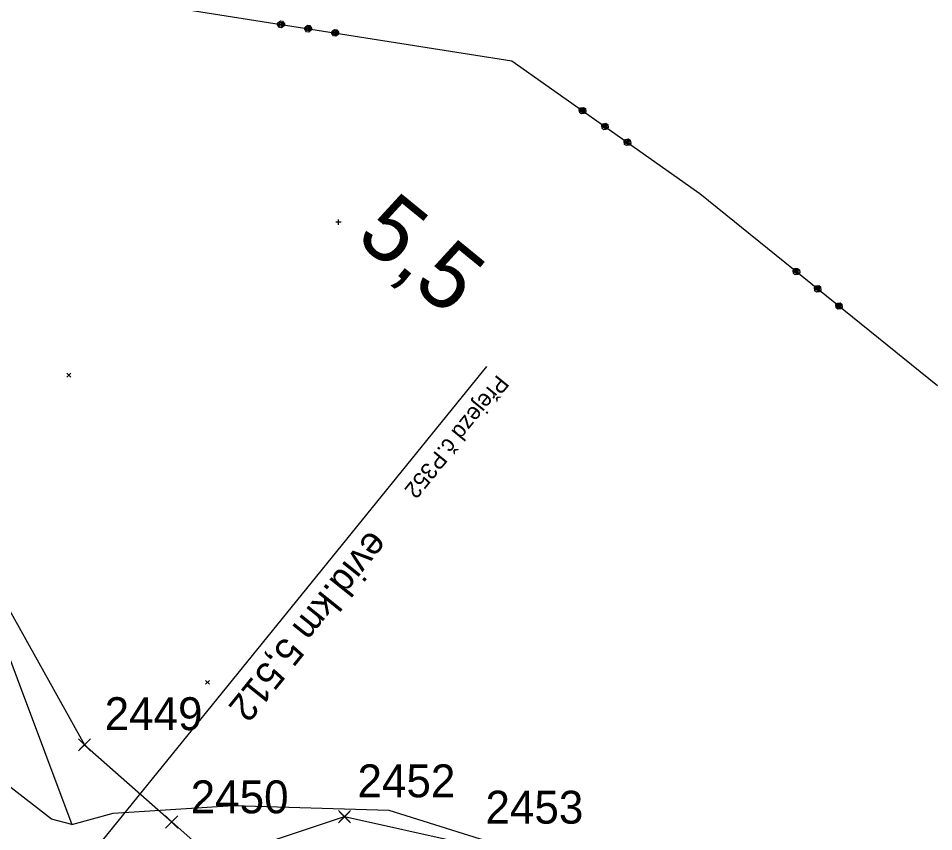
# Model space of a CAD drawing. Extents: x -866402 to -860377, y -1041908 to -1038598.
# Drawn here: x -864812.3 to -864728.8, y -1041184.8 to -1041110.6 of the extents above; entities that cross this region are included whole.
import ezdxf

# ---------------------------------------------------------------- set-up
doc = ezdxf.new("R2010")
doc.units = 0
for name, color, linetype in [('SZDC', 7, 'Continuous'), ('Vrstva 1', 7, 'Continuous'), ('Vrstva 4', 7, 'Continuous'), ('Vrstva 49', 7, 'Continuous'), ('Vrstva 60', 7, 'Continuous'), ('Vrstva 7', 7, 'Continuous')]:
    doc.layers.add(name, color=color, linetype=linetype)

msp = doc.modelspace()

# ---------------------------------------------------------------- linework, layer by layer
at = {"layer": 'SZDC'}
msp.add_lwpolyline([(-864875.011, -1041097.529), (-864834.001, -1041135.622), (-864824.11, -1041144.811), (-864806.24, -1041176.841), (-864798.286, -1041183.888), (-864794.374, -1041187.354), (-864782.521, -1041183.403), (-864771.624, -1041185.807), (-864744.425, -1041200.941), (-864739.358, -1041206.135), (-864711.79, -1041234.401), (-864706.957, -1041253.226), (-864707.405, -1041272.394), (-864707.88, -1041292.731), (-864695.12, -1041304.731)], dxfattribs=at)
at = {"layer": 'Vrstva 1'}
for p, q in [((-864804.23, -1041108.61), (-864767.26, -1041114.45)), ((-864804.23, -1041108.61), (-864767.26, -1041114.45)), ((-864788.625, -1041111.176), (-864788.593, -1041110.978)), ((-864788.625, -1041111.176), (-864788.593, -1041110.978)), ((-864788.458, -1041111.405), (-864788.625, -1041111.176)), ((-864788.458, -1041111.405), (-864788.625, -1041111.176)), ((-864788.593, -1041110.978), (-864788.365, -1041110.812)), ((-864788.593, -1041110.978), (-864788.365, -1041110.812)), ((-864788.495, -1041110.994), (-864788.526, -1041111.191)), ((-864788.495, -1041110.994), (-864788.526, -1041111.191)), ((-864788.526, -1041111.191), (-864788.443, -1041111.306)), ((-864788.526, -1041111.191), (-864788.443, -1041111.306)), ((-864788.261, -1041111.436), (-864788.458, -1041111.405)), ((-864788.261, -1041111.436), (-864788.458, -1041111.405)), ((-864788.443, -1041111.306), (-864788.38, -1041110.911)), ((-864788.443, -1041111.306), (-864788.38, -1041110.911)), ((-864788.38, -1041110.911), (-864788.183, -1041110.942)), ((-864788.38, -1041110.911), (-864788.183, -1041110.942)), ((-864788.365, -1041110.812), (-864788.167, -1041110.843)), ((-864788.365, -1041110.812), (-864788.167, -1041110.843)), ((-864788.281, -1041110.926), (-864788.344, -1041111.321)), ((-864788.281, -1041110.926), (-864788.344, -1041111.321)), ((-864788.032, -1041111.269), (-864788.261, -1041111.436)), ((-864788.032, -1041111.269), (-864788.261, -1041111.436)), ((-864788.183, -1041110.942), (-864788.245, -1041111.337)), ((-864788.183, -1041110.942), (-864788.245, -1041111.337)), ((-864788.245, -1041111.337), (-864788.131, -1041111.254)), ((-864788.245, -1041111.337), (-864788.131, -1041111.254)), ((-864788.167, -1041110.843), (-864788.001, -1041111.072)), ((-864788.167, -1041110.843), (-864788.001, -1041111.072)), ((-864788.131, -1041111.254), (-864788.1, -1041111.056)), ((-864788.131, -1041111.254), (-864788.1, -1041111.056)), ((-864788.001, -1041111.072), (-864788.032, -1041111.269)), ((-864788.001, -1041111.072), (-864788.032, -1041111.269)), ((-864786.155, -1041111.566), (-864786.124, -1041111.368)), ((-864786.155, -1041111.566), (-864786.124, -1041111.368)), ((-864785.989, -1041111.795), (-864786.155, -1041111.566)), ((-864785.989, -1041111.795), (-864786.155, -1041111.566)), ((-864786.124, -1041111.368), (-864785.895, -1041111.202)), ((-864786.124, -1041111.368), (-864785.895, -1041111.202)), ((-864786.025, -1041111.384), (-864786.056, -1041111.581)), ((-864786.025, -1041111.384), (-864786.056, -1041111.581)), ((-864786.056, -1041111.581), (-864785.973, -1041111.696)), ((-864786.056, -1041111.581), (-864785.973, -1041111.696)), ((-864785.973, -1041111.696), (-864785.911, -1041111.301)), ((-864785.973, -1041111.696), (-864785.911, -1041111.301)), ((-864785.911, -1041111.301), (-864785.713, -1041111.332)), ((-864785.911, -1041111.301), (-864785.713, -1041111.332)), ((-864785.895, -1041111.202), (-864785.698, -1041111.233)), ((-864785.895, -1041111.202), (-864785.698, -1041111.233)), ((-864785.812, -1041111.316), (-864785.874, -1041111.711)), ((-864785.812, -1041111.316), (-864785.874, -1041111.711)), ((-864785.713, -1041111.332), (-864785.776, -1041111.727)), ((-864785.713, -1041111.332), (-864785.776, -1041111.727)), ((-864785.698, -1041111.233), (-864785.531, -1041111.462)), ((-864785.698, -1041111.233), (-864785.531, -1041111.462)), ((-864785.661, -1041111.644), (-864785.63, -1041111.446)), ((-864785.661, -1041111.644), (-864785.63, -1041111.446)), ((-864785.531, -1041111.462), (-864785.563, -1041111.659)), ((-864785.531, -1041111.462), (-864785.563, -1041111.659)), ((-864783.655, -1041111.758), (-864783.426, -1041111.592)), ((-864783.655, -1041111.758), (-864783.426, -1041111.592)), ((-864783.426, -1041111.592), (-864783.228, -1041111.623)), ((-864783.426, -1041111.592), (-864783.228, -1041111.623)), ((-864783.228, -1041111.623), (-864783.062, -1041111.852)), ((-864783.228, -1041111.623), (-864783.062, -1041111.852)), ((-864785.791, -1041111.826), (-864785.989, -1041111.795)), ((-864785.791, -1041111.826), (-864785.989, -1041111.795)), ((-864785.563, -1041111.659), (-864785.791, -1041111.826)), ((-864785.563, -1041111.659), (-864785.791, -1041111.826)), ((-864785.776, -1041111.727), (-864785.661, -1041111.644)), ((-864785.776, -1041111.727), (-864785.661, -1041111.644)), ((-864783.686, -1041111.956), (-864783.655, -1041111.758)), ((-864783.686, -1041111.956), (-864783.655, -1041111.758)), ((-864783.519, -1041112.185), (-864783.686, -1041111.956)), ((-864783.519, -1041112.185), (-864783.686, -1041111.956)), ((-864783.556, -1041111.774), (-864783.587, -1041111.972)), ((-864783.556, -1041111.774), (-864783.587, -1041111.972)), ((-864783.587, -1041111.972), (-864783.504, -1041112.086)), ((-864783.587, -1041111.972), (-864783.504, -1041112.086)), ((-864783.322, -1041112.216), (-864783.519, -1041112.185)), ((-864783.322, -1041112.216), (-864783.519, -1041112.185)), ((-864783.504, -1041112.086), (-864783.441, -1041111.691)), ((-864783.504, -1041112.086), (-864783.441, -1041111.691)), ((-864783.441, -1041111.691), (-864783.244, -1041111.722)), ((-864783.441, -1041111.691), (-864783.244, -1041111.722)), ((-864783.343, -1041111.706), (-864783.405, -1041112.102)), ((-864783.343, -1041111.706), (-864783.405, -1041112.102)), ((-864783.093, -1041112.05), (-864783.322, -1041112.216)), ((-864783.093, -1041112.05), (-864783.322, -1041112.216)), ((-864783.244, -1041111.722), (-864783.306, -1041112.117)), ((-864783.244, -1041111.722), (-864783.306, -1041112.117)), ((-864783.306, -1041112.117), (-864783.192, -1041112.034)), ((-864783.306, -1041112.117), (-864783.192, -1041112.034)), ((-864783.192, -1041112.034), (-864783.161, -1041111.836)), ((-864783.192, -1041112.034), (-864783.161, -1041111.836)), ((-864783.062, -1041111.852), (-864783.093, -1041112.05)), ((-864783.062, -1041111.852), (-864783.093, -1041112.05)), ((-864767.26, -1041114.45), (-864750.13, -1041126.55)), ((-864767.26, -1041114.45), (-864750.13, -1041126.55)), ((-864761.121, -1041118.908), (-864761.005, -1041118.745)), ((-864761.121, -1041118.908), (-864761.005, -1041118.745)), ((-864761.073, -1041119.187), (-864761.121, -1041118.908)), ((-864761.073, -1041119.187), (-864761.121, -1041118.908)), ((-864760.924, -1041118.802), (-864761.039, -1041118.966)), ((-864760.924, -1041118.802), (-864761.039, -1041118.966)), ((-864761.039, -1041118.966), (-864761.015, -1041119.105)), ((-864761.039, -1041118.966), (-864761.015, -1041119.105)), ((-864761.015, -1041119.105), (-864760.784, -1041118.778)), ((-864761.015, -1041119.105), (-864760.784, -1041118.778)), ((-864761.005, -1041118.745), (-864760.727, -1041118.697)), ((-864761.005, -1041118.745), (-864760.727, -1041118.697)), ((-864760.703, -1041118.836), (-864760.934, -1041119.163)), ((-864760.703, -1041118.836), (-864760.934, -1041119.163)), ((-864760.621, -1041118.894), (-864760.852, -1041119.221)), ((-864760.621, -1041118.894), (-864760.852, -1041119.221)), ((-864760.784, -1041118.778), (-864760.621, -1041118.894)), ((-864760.784, -1041118.778), (-864760.621, -1041118.894)), ((-864760.727, -1041118.697), (-864760.563, -1041118.812)), ((-864760.727, -1041118.697), (-864760.563, -1041118.812)), ((-864760.712, -1041119.197), (-864760.597, -1041119.033)), ((-864760.712, -1041119.197), (-864760.597, -1041119.033)), ((-864760.515, -1041119.091), (-864760.631, -1041119.254)), ((-864760.515, -1041119.091), (-864760.631, -1041119.254)), ((-864760.563, -1041118.812), (-864760.515, -1041119.091)), ((-864760.563, -1041118.812), (-864760.515, -1041119.091)), ((-864760.91, -1041119.302), (-864761.073, -1041119.187)), ((-864760.91, -1041119.302), (-864761.073, -1041119.187)), ((-864760.631, -1041119.254), (-864760.91, -1041119.302)), ((-864760.631, -1041119.254), (-864760.91, -1041119.302)), ((-864760.852, -1041119.221), (-864760.712, -1041119.197)), ((-864760.852, -1041119.221), (-864760.712, -1041119.197)), ((-864759.079, -1041120.35), (-864758.964, -1041120.187)), ((-864759.079, -1041120.35), (-864758.964, -1041120.187)), ((-864759.031, -1041120.629), (-864759.079, -1041120.35)), ((-864759.031, -1041120.629), (-864759.079, -1041120.35)), ((-864758.868, -1041120.745), (-864759.031, -1041120.629)), ((-864758.868, -1041120.745), (-864759.031, -1041120.629)), ((-864758.882, -1041120.245), (-864758.997, -1041120.408)), ((-864758.882, -1041120.245), (-864758.997, -1041120.408)), ((-864758.997, -1041120.408), (-864758.973, -1041120.547)), ((-864758.997, -1041120.408), (-864758.973, -1041120.547)), ((-864758.973, -1041120.547), (-864758.742, -1041120.221)), ((-864758.973, -1041120.547), (-864758.742, -1041120.221)), ((-864758.964, -1041120.187), (-864758.685, -1041120.139)), ((-864758.964, -1041120.187), (-864758.685, -1041120.139)), ((-864758.661, -1041120.278), (-864758.892, -1041120.605)), ((-864758.661, -1041120.278), (-864758.892, -1041120.605)), ((-864758.589, -1041120.697), (-864758.868, -1041120.745)), ((-864758.589, -1041120.697), (-864758.868, -1041120.745)), ((-864758.579, -1041120.336), (-864758.81, -1041120.663)), ((-864758.579, -1041120.336), (-864758.81, -1041120.663)), ((-864758.81, -1041120.663), (-864758.671, -1041120.639)), ((-864758.81, -1041120.663), (-864758.671, -1041120.639)), ((-864758.742, -1041120.221), (-864758.579, -1041120.336)), ((-864758.742, -1041120.221), (-864758.579, -1041120.336)), ((-864758.685, -1041120.139), (-864758.521, -1041120.254)), ((-864758.685, -1041120.139), (-864758.521, -1041120.254)), ((-864758.671, -1041120.639), (-864758.555, -1041120.476)), ((-864758.671, -1041120.639), (-864758.555, -1041120.476)), ((-864758.473, -1041120.533), (-864758.589, -1041120.697)), ((-864758.473, -1041120.533), (-864758.589, -1041120.697)), ((-864758.521, -1041120.254), (-864758.473, -1041120.533)), ((-864758.521, -1041120.254), (-864758.473, -1041120.533)), ((-864757.037, -1041121.793), (-864756.922, -1041121.629)), ((-864757.037, -1041121.793), (-864756.922, -1041121.629)), ((-864756.922, -1041121.629), (-864756.643, -1041121.581)), ((-864756.922, -1041121.629), (-864756.643, -1041121.581)), ((-864756.643, -1041121.581), (-864756.479, -1041121.697)), ((-864756.643, -1041121.581), (-864756.479, -1041121.697)), ((-864756.989, -1041122.072), (-864757.037, -1041121.793)), ((-864756.989, -1041122.072), (-864757.037, -1041121.793)), ((-864756.826, -1041122.187), (-864756.989, -1041122.072)), ((-864756.826, -1041122.187), (-864756.989, -1041122.072)), ((-864756.84, -1041121.687), (-864756.955, -1041121.85)), ((-864756.84, -1041121.687), (-864756.955, -1041121.85)), ((-864756.955, -1041121.85), (-864756.931, -1041121.99)), ((-864756.955, -1041121.85), (-864756.931, -1041121.99)), ((-864756.931, -1041121.99), (-864756.701, -1041121.663)), ((-864756.931, -1041121.99), (-864756.701, -1041121.663)), ((-864756.619, -1041121.721), (-864756.85, -1041122.048)), ((-864756.619, -1041121.721), (-864756.85, -1041122.048)), ((-864756.547, -1041122.139), (-864756.826, -1041122.187)), ((-864756.547, -1041122.139), (-864756.826, -1041122.187)), ((-864756.537, -1041121.779), (-864756.768, -1041122.105)), ((-864756.537, -1041121.779), (-864756.768, -1041122.105)), ((-864756.768, -1041122.105), (-864756.629, -1041122.081)), ((-864756.768, -1041122.105), (-864756.629, -1041122.081)), ((-864756.701, -1041121.663), (-864756.537, -1041121.779)), ((-864756.701, -1041121.663), (-864756.537, -1041121.779)), ((-864756.629, -1041122.081), (-864756.513, -1041121.918)), ((-864756.629, -1041122.081), (-864756.513, -1041121.918)), ((-864756.432, -1041121.976), (-864756.547, -1041122.139)), ((-864756.432, -1041121.976), (-864756.547, -1041122.139)), ((-864756.479, -1041121.697), (-864756.432, -1041121.976)), ((-864756.479, -1041121.697), (-864756.432, -1041121.976)), ((-864750.13, -1041126.55), (-864728.47, -1041144.08)), ((-864750.13, -1041126.55), (-864728.47, -1041144.08)), ((-864741.617, -1041133.568), (-864741.491, -1041133.412)), ((-864741.617, -1041133.568), (-864741.491, -1041133.412)), ((-864741.587, -1041133.849), (-864741.617, -1041133.568)), ((-864741.587, -1041133.849), (-864741.617, -1041133.568)), ((-864741.432, -1041133.975), (-864741.587, -1041133.849)), ((-864741.432, -1041133.975), (-864741.587, -1041133.849)), ((-864741.413, -1041133.475), (-864741.539, -1041133.631)), ((-864741.413, -1041133.475), (-864741.539, -1041133.631)), ((-864741.539, -1041133.631), (-864741.524, -1041133.771)), ((-864741.539, -1041133.631), (-864741.524, -1041133.771)), ((-864741.524, -1041133.771), (-864741.272, -1041133.46)), ((-864741.524, -1041133.771), (-864741.272, -1041133.46)), ((-864741.491, -1041133.412), (-864741.21, -1041133.383)), ((-864741.491, -1041133.412), (-864741.21, -1041133.383)), ((-864741.195, -1041133.523), (-864741.446, -1041133.834)), ((-864741.195, -1041133.523), (-864741.446, -1041133.834)), ((-864741.15, -1041133.945), (-864741.432, -1041133.975)), ((-864741.15, -1041133.945), (-864741.432, -1041133.975)), ((-864741.117, -1041133.586), (-864741.369, -1041133.897)), ((-864741.117, -1041133.586), (-864741.369, -1041133.897)), ((-864741.369, -1041133.897), (-864741.228, -1041133.882)), ((-864741.369, -1041133.897), (-864741.228, -1041133.882)), ((-864741.272, -1041133.46), (-864741.117, -1041133.586)), ((-864741.272, -1041133.46), (-864741.117, -1041133.586)), ((-864741.228, -1041133.882), (-864741.102, -1041133.727)), ((-864741.228, -1041133.882), (-864741.102, -1041133.727)), ((-864741.21, -1041133.383), (-864741.054, -1041133.509)), ((-864741.21, -1041133.383), (-864741.054, -1041133.509)), ((-864741.024, -1041133.79), (-864741.15, -1041133.945)), ((-864741.024, -1041133.79), (-864741.15, -1041133.945)), ((-864741.054, -1041133.509), (-864741.024, -1041133.79)), ((-864741.054, -1041133.509), (-864741.024, -1041133.79)), ((-864739.673, -1041135.141), (-864739.548, -1041134.985)), ((-864739.673, -1041135.141), (-864739.548, -1041134.985)), ((-864739.548, -1041134.985), (-864739.266, -1041134.955)), ((-864739.548, -1041134.985), (-864739.266, -1041134.955)), ((-864739.266, -1041134.955), (-864739.111, -1041135.081)), ((-864739.266, -1041134.955), (-864739.111, -1041135.081)), ((-864739.644, -1041135.422), (-864739.673, -1041135.141)), ((-864739.644, -1041135.422), (-864739.673, -1041135.141)), ((-864739.488, -1041135.548), (-864739.644, -1041135.422)), ((-864739.488, -1041135.548), (-864739.644, -1041135.422)), ((-864739.47, -1041135.048), (-864739.596, -1041135.204)), ((-864739.47, -1041135.048), (-864739.596, -1041135.204)), ((-864739.596, -1041135.204), (-864739.581, -1041135.344)), ((-864739.596, -1041135.204), (-864739.581, -1041135.344)), ((-864739.581, -1041135.344), (-864739.329, -1041135.033)), ((-864739.581, -1041135.344), (-864739.329, -1041135.033)), ((-864739.251, -1041135.096), (-864739.503, -1041135.407)), ((-864739.251, -1041135.096), (-864739.503, -1041135.407)), ((-864739.207, -1041135.518), (-864739.488, -1041135.548)), ((-864739.207, -1041135.518), (-864739.488, -1041135.548)), ((-864739.174, -1041135.159), (-864739.425, -1041135.47)), ((-864739.174, -1041135.159), (-864739.425, -1041135.47)), ((-864739.425, -1041135.47), (-864739.285, -1041135.455)), ((-864739.425, -1041135.47), (-864739.285, -1041135.455)), ((-864739.329, -1041135.033), (-864739.174, -1041135.159)), ((-864739.329, -1041135.033), (-864739.174, -1041135.159)), ((-864739.285, -1041135.455), (-864739.159, -1041135.3)), ((-864739.285, -1041135.455), (-864739.159, -1041135.3)), ((-864739.081, -1041135.363), (-864739.207, -1041135.518)), ((-864739.081, -1041135.363), (-864739.207, -1041135.518)), ((-864739.111, -1041135.081), (-864739.081, -1041135.363)), ((-864739.111, -1041135.081), (-864739.081, -1041135.363)), ((-864737.73, -1041136.713), (-864737.604, -1041136.558)), ((-864737.73, -1041136.713), (-864737.604, -1041136.558)), ((-864737.526, -1041136.621), (-864737.652, -1041136.776)), ((-864737.526, -1041136.621), (-864737.652, -1041136.776)), ((-864737.637, -1041136.917), (-864737.386, -1041136.606)), ((-864737.637, -1041136.917), (-864737.386, -1041136.606)), ((-864737.604, -1041136.558), (-864737.323, -1041136.528)), ((-864737.604, -1041136.558), (-864737.323, -1041136.528)), ((-864737.308, -1041136.669), (-864737.56, -1041136.98)), ((-864737.308, -1041136.669), (-864737.56, -1041136.98)), ((-864737.386, -1041136.606), (-864737.23, -1041136.732)), ((-864737.386, -1041136.606), (-864737.23, -1041136.732)), ((-864737.323, -1041136.528), (-864737.167, -1041136.654)), ((-864737.323, -1041136.528), (-864737.167, -1041136.654)), ((-864737.167, -1041136.654), (-864737.138, -1041136.935)), ((-864737.167, -1041136.654), (-864737.138, -1041136.935)), ((-864737.7, -1041136.995), (-864737.73, -1041136.713)), ((-864737.7, -1041136.995), (-864737.73, -1041136.713)), ((-864737.545, -1041137.12), (-864737.7, -1041136.995)), ((-864737.545, -1041137.12), (-864737.7, -1041136.995)), ((-864737.652, -1041136.776), (-864737.637, -1041136.917)), ((-864737.652, -1041136.776), (-864737.637, -1041136.917)), ((-864737.264, -1041137.091), (-864737.545, -1041137.12)), ((-864737.264, -1041137.091), (-864737.545, -1041137.12)), ((-864737.23, -1041136.732), (-864737.482, -1041137.043)), ((-864737.23, -1041136.732), (-864737.482, -1041137.043)), ((-864737.482, -1041137.043), (-864737.341, -1041137.028)), ((-864737.482, -1041137.043), (-864737.341, -1041137.028)), ((-864737.341, -1041137.028), (-864737.216, -1041136.872)), ((-864737.341, -1041137.028), (-864737.216, -1041136.872)), ((-864737.138, -1041136.935), (-864737.264, -1041137.091)), ((-864737.138, -1041136.935), (-864737.264, -1041137.091))]:
    msp.add_line(p, q, dxfattribs=at)
at = {"layer": 'Vrstva 4'}
msp.add_line((-864806.506, -1041187.914), (-864769.54, -1041142.338), dxfattribs=at)
at = {"layer": 'Vrstva 49'}
for p, q in [((-864783.085, -1041129.416), (-864783.083, -1041128.916)), ((-864782.834, -1041129.167), (-864783.334, -1041129.165)), ((-864807.841, -1041142.947), (-864807.487, -1041143.301)), ((-864807.841, -1041143.301), (-864807.487, -1041142.947)), ((-864795.207, -1041170.973), (-864794.853, -1041171.327)), ((-864795.207, -1041171.327), (-864794.853, -1041170.973))]:
    msp.add_line(p, q, dxfattribs=at)
for points in [[(-864897.758, -1041076.238), (-864888.348, -1041086.949), (-864877.441, -1041097.612), (-864860.332, -1041113.848), (-864846.012, -1041124.758), (-864827.906, -1041142.136), (-864819.379, -1041153.851), (-864814.896, -1041164.146), (-864807.385, -1041184.11)], [(-864807.385, -1041184.11), (-864809.232, -1041183.638), (-864817.441, -1041177.275), (-864827.962, -1041168.612)], [(-864807.385, -1041184.11), (-864803.632, -1041183.085), (-864792.676, -1041182.388), (-864778.478, -1041182.825), (-864767.043, -1041186.39), (-864756.405, -1041192.559), (-864754.298, -1041193.343), (-864736.853, -1041202.156), (-864729.137, -1041206.153)]]:
    msp.add_lwpolyline(points, dxfattribs=at)
at = {"layer": 'Vrstva 60'}
for p, q in [((-864805.79, -1041177.291), (-864806.79, -1041176.291)), ((-864805.79, -1041176.391), (-864806.79, -1041177.391)), ((-864806.69, -1041177.291), (-864805.69, -1041176.291)), ((-864806.69, -1041176.391), (-864805.69, -1041177.391)), ((-864806.24, -1041176.841), (-864806.24, -1041176.841)), ((-864797.836, -1041184.338), (-864798.836, -1041183.338)), ((-864798.736, -1041184.338), (-864797.736, -1041183.338)), ((-864782.071, -1041183.853), (-864783.071, -1041182.853)), ((-864782.071, -1041182.953), (-864783.071, -1041183.953)), ((-864782.971, -1041183.853), (-864781.971, -1041182.853)), ((-864782.971, -1041182.953), (-864781.971, -1041183.953)), ((-864782.521, -1041183.403), (-864782.521, -1041183.403)), ((-864797.836, -1041183.438), (-864798.836, -1041184.438)), ((-864798.736, -1041183.438), (-864797.736, -1041184.438)), ((-864798.286, -1041183.888), (-864798.286, -1041183.888))]:
    msp.add_line(p, q, dxfattribs=at)

# ---------------------------------------------------------------- texts
at = {"layer": 'Vrstva 4'}
for s, height, rotation, p in [('Přejezd č.P352', 1.5, 230.95541, (-864768.582, -1041143.01)), ('evid.km 5,512', 2.5, 231.23165, (-864780.197, -1041157.162))]:
    msp.add_text(s, height=height, rotation=rotation, dxfattribs=at).set_placement(p)
at = {"layer": 'Vrstva 60'}
for s, p in [('2449', (-864804.4, -1041175.508)), ('2452', (-864781.345, -1041181.637)), ('2450', (-864796.554, -1041183.097)), ('2453', (-864769.675, -1041184.041))]:
    msp.add_text(s, height=3, dxfattribs=at).set_placement(p)
at = {"layer": 'Vrstva 7'}
msp.add_text('5,5', height=6, rotation=320.74794, dxfattribs=at).set_placement((-864781.658, -1041130.79))

doc.saveas('drawing.dxf')
